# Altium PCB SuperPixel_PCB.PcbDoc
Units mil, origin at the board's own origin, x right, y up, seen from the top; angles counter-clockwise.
Board outline 3155 x 3149.61 mil, 2 copper layers (Top Layer, Bottom Layer); 61 components, 44 nets, 211 pads, 90 vias.
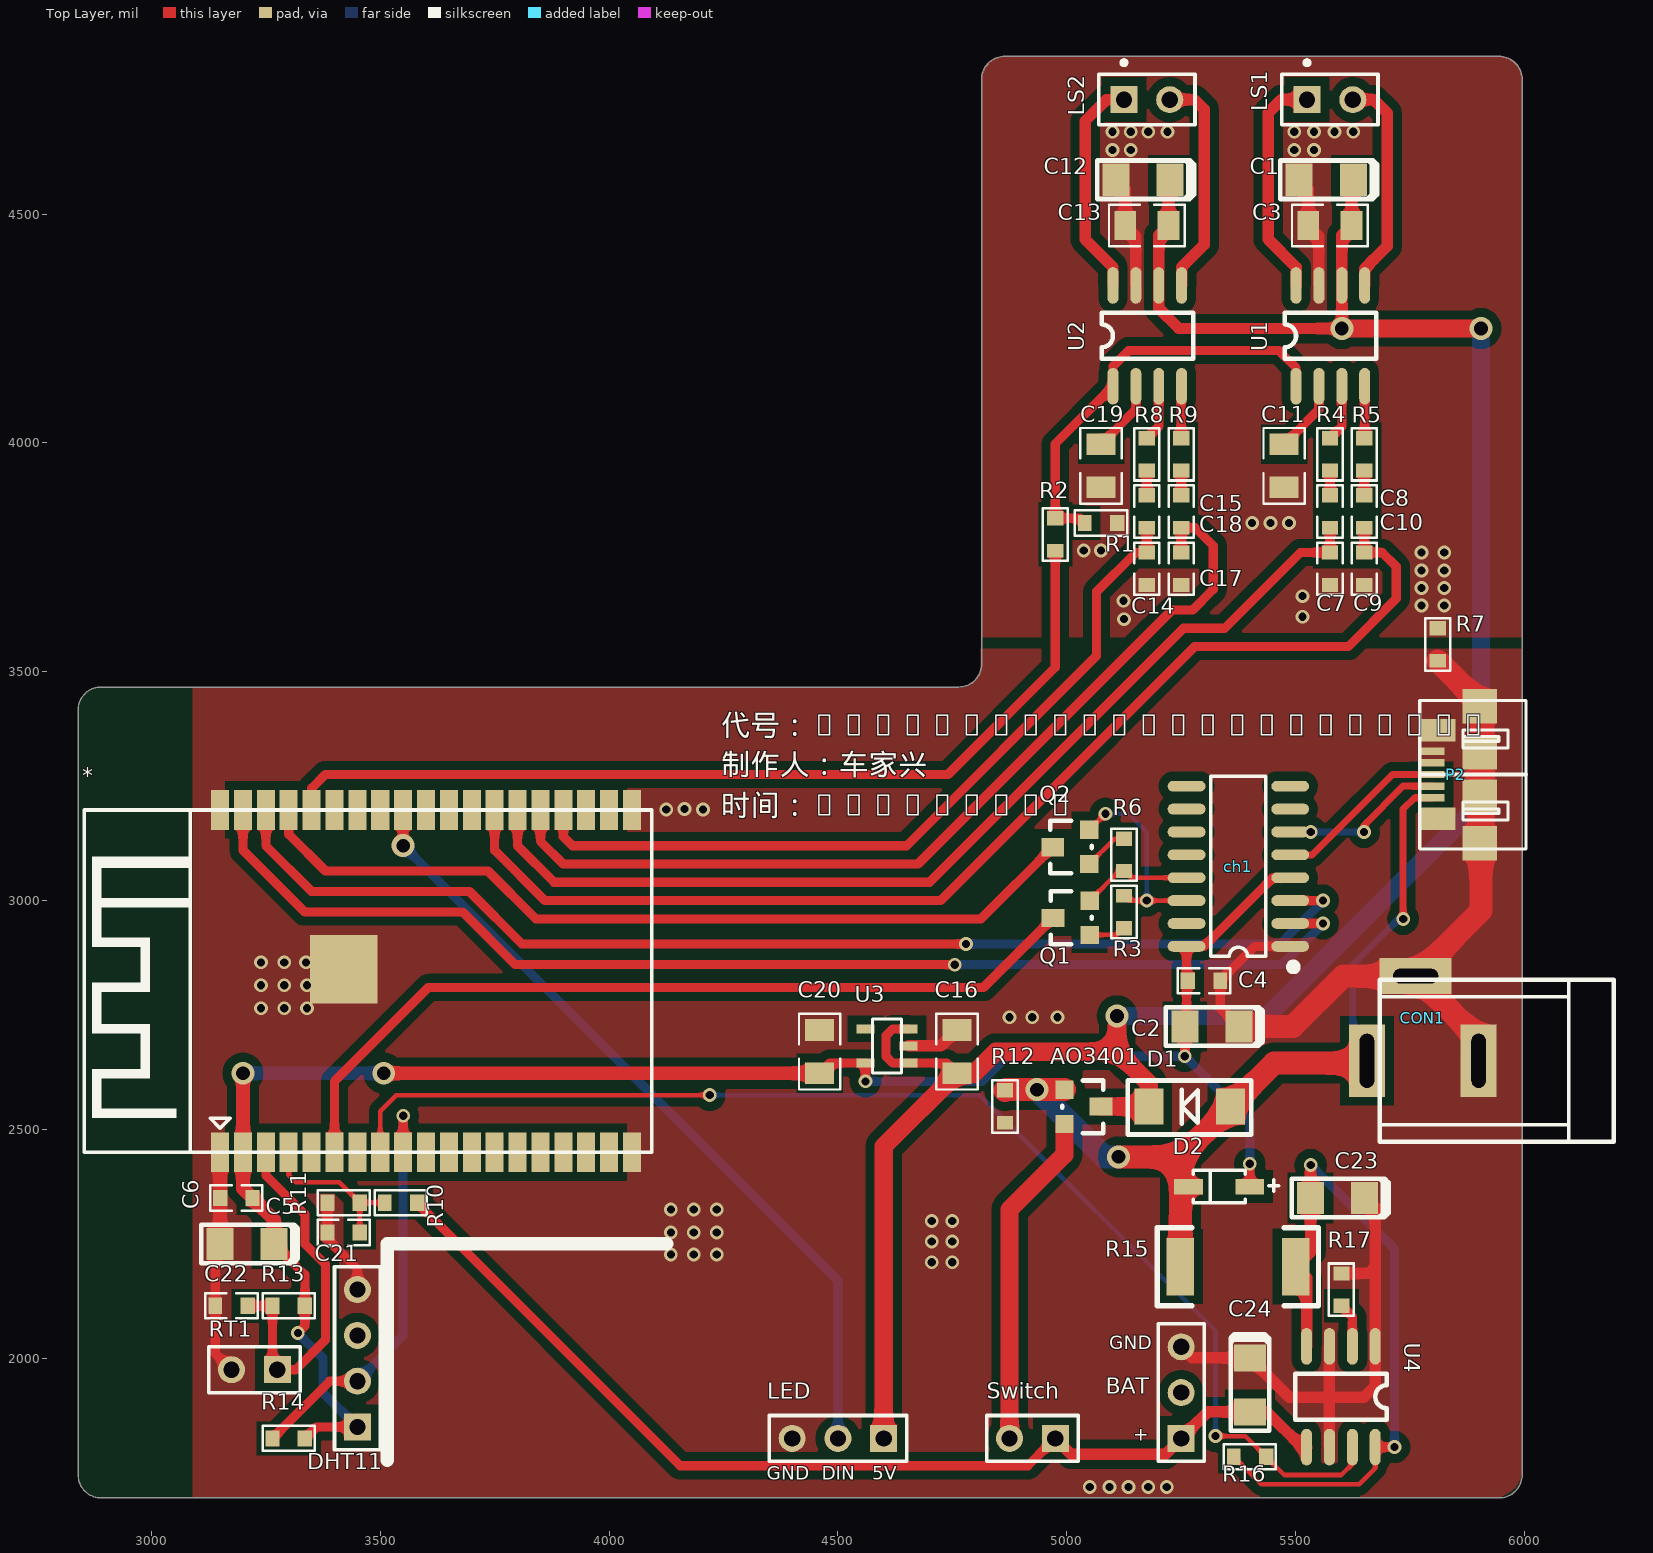
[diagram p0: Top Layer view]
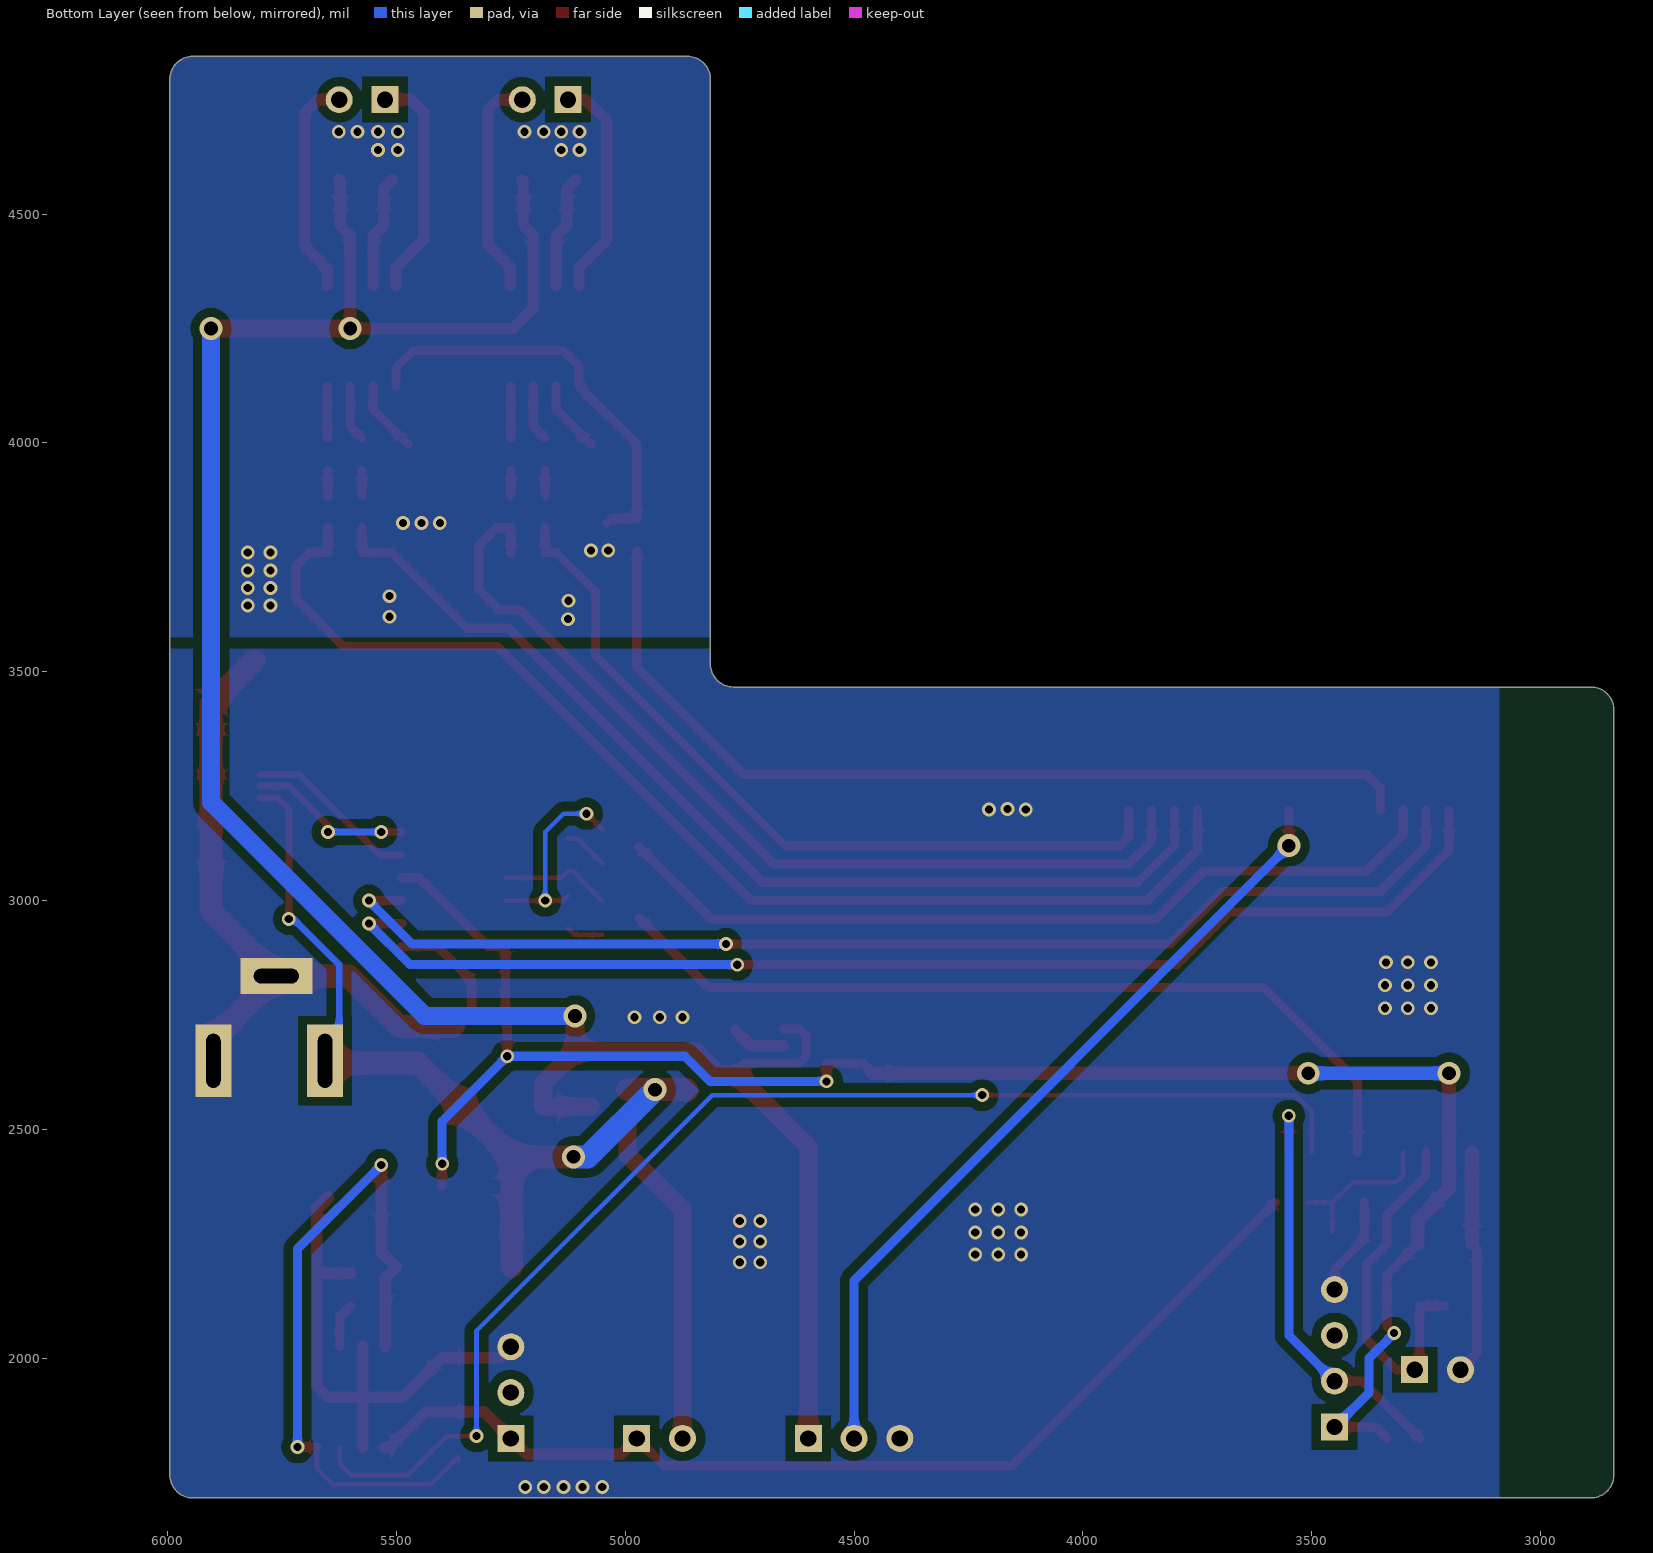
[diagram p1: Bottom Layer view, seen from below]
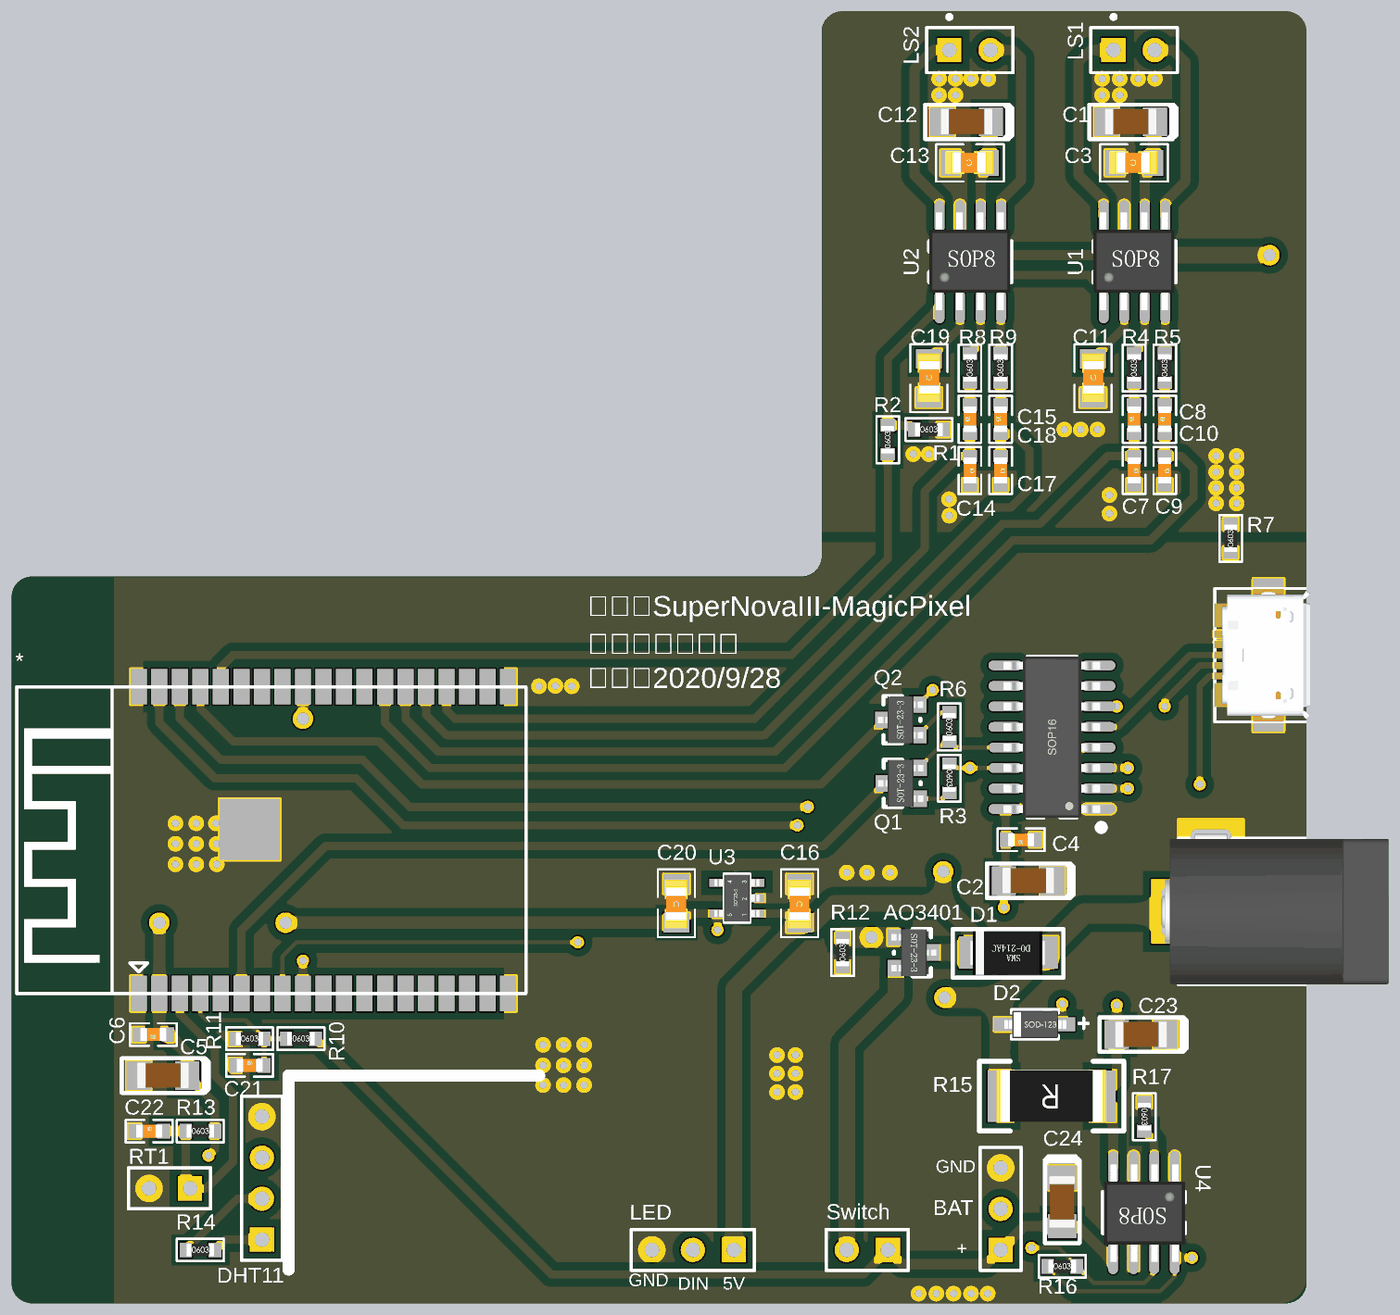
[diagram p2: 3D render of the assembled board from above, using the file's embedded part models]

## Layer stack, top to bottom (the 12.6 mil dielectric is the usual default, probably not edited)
Top Solder: solder mask 0.4, Solder Resist, Dk 3.5
Top Layer: signal copper 1.4
Dielectric 1: dielectric 12.6, FR-4, Dk 4.8
Bottom Layer: signal copper 1.4
Bottom Solder: solder mask 0.4, Solder Resist, Dk 3.5

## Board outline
2840,1745 ccw(c2890,1745) 2890,1695 5945,1695 ccw(c5945,1745) 5995,1745 5995,4794.61 ccw(c5945,4794.61) 5945,4844.61 4863.9,4844.61 ccw(c4863.9,4794.61) 4813.9,4794.61 4813.9,3516.65 cw(c4763.9,3516.65) 4763.9,3466.65 2890,3466.65 ccw(c2890,3416.65) 2840,3416.65

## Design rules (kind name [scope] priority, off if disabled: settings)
Clearance [All] p1: gap=10 ignorepadtopadclearanceinfootprint=FALSE except(0: Arc-Hole Track-Hole SMDPad-Hole THPad-Hole Via-Hole Fill-Hole Poly-Hole Region-Hole Text-Hole; 20: Arc-Poly Track-Poly SMDPad-Poly THPad-Poly Via-Poly Fill-Poly Poly-Poly)
PolygonConnect [All] p1: connectstyle=Direct reliefconductorwidth=10 reliefentries=4 polygonreliefangle="90 Angle" airgapwidth=10
RoutingVias [All] p1: holewidth=28 width=50 viastyle="Through Hole" minholewidth=28 minwidth=50 maxholewidth=28 maxwidth=50
SolderMaskExpansion [All] p1: expansion=4
Width [All] p1: maxlimit=50 minlimit=10 preferedwidth=10
30 further rules are at their usual default settings.

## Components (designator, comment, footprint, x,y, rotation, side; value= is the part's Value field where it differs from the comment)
* "ESP32-A1S Module" "ESP32-A1S Module" 3475,2825 r90 top
AO3401 "MOSFET-P" sot23 4994.37,2591.88 r270 top
BAT "Header 3" HDR1X3 5250,1825 r90 top (schematic designator P1)
C1 "Cap" 1206c 5625,4575 r180 top value=10uF
C2 "Cap" 1206c 5375,2725 r180 top value=10uF
C3 "Cap" 0805-1c 5575,4475 r180 top value=1uF
C4 "Cap" 0603c 5300,2825 r180 top value=100nF
C5 "Cap" 1206c 3267.11,2250 r180 top value=10uF
C6 "Cap" 0603c 3185.43,2350 r180 top value=0.1uF
C7 "Cap" 0603c 5575,3725 r270 top value=0.1uF
C8 "Cap" 0603c 5575,3850 r90 top value=0.1uF
C9 "Cap" 0603c 5650,3725 r270 top value=0.1uF
C10 "Cap" 0603c 5650,3850 r90 top value=0.1uF
C11 "Cap" 0805-1c 5475,3950 r90 top value=1uF
C12 "Cap" 1206c 5225,4575 r180 top value=10uF
C13 "Cap" 0805-1c 5175,4475 r180 top value=1uF
C14 "Cap" 0603c 5175,3725 r270 top value=0.1uF
C15 "Cap" 0603c 5175,3850 r90 top value=0.1uF
C16 "Cap" 0805-1c 4760,2670 r270 top value=1uF
C17 "Cap" 0603c 5250,3725 r270 top value=0.1uF
C18 "Cap" 0603c 5250,3850 r90 top value=0.1uF
C19 "Cap" 0805-1c 5075,3950 r90 top value=1uF
C20 "Cap" 0805-1c 4460,2670 r270 top value=1uF
C21 "Cap" 0603c 3420,2275 r0 top value=100nF
C22 "Cap" 0603c 3175,2114.57 r0 top value=0.1uF
C23 "Cap" 1206c 5650,2350 r180 top value=10uF
C24 "Cap" 1206c 5400,2000 r270 top value=10uF
ch1 "CH340C" SOP16_M 5375,3075 r180 top
CON1 "3.5*1.3" DC-005 5900,2650 r0 top
D1 "SS54" SMA 5350,2550 r180 top
D2 "MBR0520" SOD123 5400,2375 r0 top
DHT11 "Header 4" HDR1X4 3450,1850 r90 top
LED "Header 3" HDR1X3 4600,1825 r180 top
LS1 "Speaker" PIN2 5525,4750 r0 top
LS2 "Speaker" PIN2 5125,4750 r0 top
P2 "Header 6" USB-MICRO 5850,3275 r90 top
Q1 "s8050" sot-23 5050.63,2920.12 r90 top
Q2 "s8050" sot-23 5050,3075 r90 top
R1 "Res1" 0603r 5075,3825 r0 top value=10k
R2 "Res1" 0603r 4975,3800 r90 top value=1K
R3 "Res1" 0603r 5125,2975 r270 top value=10k
R4 "Res1" 0603r 5575,3975 r90 top value=30k
R5 "Res1" 0603r 5650,3975 r90 top value=30k
R6 "Res1" 0603r 5125,3100 r90 top value=10k
R7 "Res1" 0603r 5810.5,3559.57 r90 top value=0
R8 "Res1" 0603r 5175,3975 r90 top value=30k
R9 "Res1" 0603r 5250,3975 r90 top value=30k
R10 "Res1" 0603r 3545,2340 r0 top value=10k
R11 "Res1" 0603r 3420,2340 r0 top value=1k
R12 "Res1" 0603r 4865,2550 r90 top value=10k
R13 "Res1" 0603r 3300,2114.57 r0 top value=10k
R14 "Res1" 0603r 3300,1825 r0 top value=10k
R15 "Res1" 2512-r 5500,2200 r0 top value=0.4
R16 "Res1" 0603r 5400,1785 r0 top value=10k
R17 "Res1" 0603r 5600,2150 r270 top value=5k
RT1 "Res Thermal" HDR1X2 3275,1975 r180 top
Switch "SW-SPST" HDR1X2 4975,1825 r180 top (schematic designator S1)
U1 "NS4150" SOP8 5500,4125 r90 top
U2 "NS4150" SOP8 5100,4125 r90 top
U3 "RT9013-33GB" sot23-5 4654.49,2645 r270 top
U4 "TP4056" SOP8 5675,2025 r270 top

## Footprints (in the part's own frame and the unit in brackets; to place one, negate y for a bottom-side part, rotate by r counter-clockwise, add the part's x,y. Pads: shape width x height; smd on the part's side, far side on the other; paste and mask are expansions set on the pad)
0603c [mm]
  rect 0.762x0.9 smd: 1(-0.9,0)
  rect 0.8x0.9 smd: 2(0.9,0)
  silkscreen extent -1.45,-0.7 1.45,0.7, body extent -0.8,-0.4 0.8,0.4, height 0.3
0603r [mm]
  rect 0.762x0.9 smd: 1(-0.9,0)
  rect 0.8x0.9 smd: 2(0.9,0)
  silkscreen extent -1.45,-0.7 1.45,0.7, body extent -0.85,-0.4 0.85,0.4, height 0.56
0805-1c [mm]
  rect 1.2x1.6 smd: 1(-1.2,0) 2(1.2,0)
  silkscreen extent -2.1,-1.15 2.1,1.15, body extent -1.46,-0.72 1.54,0.68, height 0.93
1206c [mil]
  rect 59.06x70 smd: 1(-1,0) 2(117.11,0)
  silkscreen extent -53,-42 159,42, body extent -5,-32 121,31, height 37
2512-r [mil]
  rect 60x125 smd: 1(0,0) 2(-251.97,0)
  silkscreen extent -302,-85 50,85, body extent -260,-65 8,65, height 25
DC-005 [mm] "5.5*2.1mm，DC30V,2.5A"
  rect 2x4 hole 0.8 slot 3 at 90 deg: 1(-6.2,0) 2(0,0)
  rect 4x2 hole 0.8 slot 2.5 at 0 deg: 3(-3.5,4.7)
  silkscreen extent -5.48,-4.5 7.5,4.5, body extent -6.55,-4.5 7.5,4.8, height 11.2
"ESP32-A1S Module" [mm]
  rect 2.2x1 smd: 1(-9.525,8.255) 2(-9.525,6.985) 3(-9.525,5.715) 4(-9.525,4.445) 5(-9.525,3.175) 6(-9.525,1.905) 7(-9.525,0.635) 8(-9.525,-0.635) 9(-9.525,-1.905) 10(-9.525,-3.175) 11(-9.525,-4.445) 12(-9.525,-5.715) 13(-9.525,-6.985) 14(-9.525,-8.255) 15(-9.525,-9.525) 16(-9.525,-10.795) 17(-9.525,-12.065) 18(-9.525,-13.335) 19(-9.525,-14.605) 20(9.475,-14.605) 21(9.475,-13.335) 22(9.475,-12.065) 23(9.475,-10.795) 24(9.475,-9.525) 25(9.475,-8.255) 26(9.475,-6.985) 27(9.475,-5.715) 28(9.475,-4.445) 29(9.475,-3.175) 30(9.475,-1.905) 31(9.475,-0.635) 32(9.475,0.635) 33(9.475,1.905) 34(9.475,3.175) 35(9.475,4.445) 36(9.475,5.715) 37(9.475,6.985) 38(9.475,8.255)
  rect 3.785x3.759 smd: 39(0.635,1.397)
  silkscreen extent -9.53,-15.7 9.48,15.8
HDR1X2 [mm] "Connector; Header; 2 Position"
  rect 1.5x1.5 hole 0.9: 1(0,0)
  round 1.5 hole 0.9: 2(2.54,0)
  silkscreen extent -1.27,-1.27 3.81,1.27
HDR1X3 [mm] "Connector; Header; 3 Position"
  rect 1.5x1.5 hole 0.9: 1(0,0)
  round 1.5 hole 0.9: 2(2.54,0) 3(5.08,0)
  silkscreen extent -1.27,-1.27 6.35,1.27
HDR1X4 [mm] "Connector; Header; 4 Position"
  rect 1.5x1.5 hole 0.9: 1(0,0)
  round 1.5 hole 0.9: 2(2.54,0) 3(5.08,0) 4(7.62,0)
  silkscreen extent -1.27,-1.27 8.89,1.27
PIN2 [mm] "Photosensitive Diode; 2 Leads"
  rect 1.5x1.5 hole 0.9: 1(0,0)
  round 1.5 hole 0.9: 2(2.54,0)
  silkscreen extent -1.4,-1.4 3.94,2.17
SMA [mil] "DO-214AC(2010)"
  rect 63x78.74 smd: 1(-8,0) 2(170.56,0)
  silkscreen extent -53,-57 217,61, body extent -8,-52 174,54, height 94
SOD123 [mm] "1206"
  rect 1.6x0.85 smd: 1(0,0) 2(-3.4,0)
  silkscreen extent -3.15,-0.9 1.6,0.9, body extent -3.6,-0.85 0.25,0.85, height 1.42
SOP8 [mil]
  oval 80x24 smd: 1(-1,-1) 2(-1,-51) 3(-1,-101) 4(-1,-151) 5(219,-151) 6(219,-101) 7(219,-51) 8(219,-1)
  silkscreen extent 59,-176 159,24, body extent -9,-174 229,24, height 63
SOP16_M [mm] "10.3*6.2*1.8mm（长宽高）"
  oval 2.1x0.6 smd: 1(-2.875,4.445) 2(-2.875,3.175) 3(-2.875,1.905) 4(-2.875,0.635) 5(-2.875,-0.635) 6(-2.875,-1.905) 7(-2.875,-3.175) 8(-2.875,-4.445) 9(2.875,-4.445) 10(2.875,-3.175) 11(2.875,-1.905) 12(2.875,-0.635) 13(2.875,0.635) 14(2.875,1.905) 15(2.875,3.175) 16(2.875,4.445)
  silkscreen extent -3.2,-5 1.52,5.74, body extent -3,-5 3,5, height 1.9
sot23 [mil]
  rect 40x40 smd: 1(4.88,0.63) 3(79.88,0.63)
  rect 40x50 smd: 2(41.88,80.63)
  silkscreen extent -15,-4 100,86, body extent -15,-11 99,99, height 47
sot23-5 [mm]
  rect 0.5x1 smd: 1(0,0) 2(-0.95,0) 3(-1.9,0) 4(-1.9,-2.4) 5(0,-2.4)
  silkscreen extent -2.45,-2 0.55,-0.4, body extent -2.4,-2.6 0.5,0.2, height 1.09
sot-23 [mil]
  rect 40x40 smd: 1(4.88,0.63) 2(79.88,0.63)
  rect 40x50 smd: 3(41.88,80.63)
  silkscreen extent -15,-4 100,86, body extent -15,-11 99,99, height 47
USB-MICRO [mm]
  rect 1.9x1.9 smd: 0(-3.797,-1.334) 0(-1.206,-1.333) 0(1.232,-1.333) 0(3.797,-1.333)
  rect 1.25x2 smd: 0(-2.451,1.003) 0(2.476,1.003)
  rect 0.4x1.4 smd: 1(-1.283,1.333) 2(-0.635,1.333) 3(0.013,1.333) 4(0.66,1.333) 5(1.308,1.333)
  silkscreen extent -4.13,-3.91 4.13,1.99, body extent -4.1,-3.91 4.1,2.02, height 2.77

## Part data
AO3401: "P-Channel MOSFET"
BAT LED: "Header, 3-Pin"
C1 C2 C3 C4 C5 C6 C7 C8 C9 C10 C11 C12 C13 C14 C15 C16 C17 C18 C19 C20 C21 C22 C23 C24: "Capacitor"
ch1: library part CH340G, "串口转USB"
CON1: library part P-DC, "低压电源接口"
D1 D2: library part "D Schottky", "Schottky Diode"
DHT11: "Header, 4-Pin"
LS1 LS2: "Loudspeaker"
P2: "Header, 6-Pin"
Q1 Q2: library part NPN, "NPN Bipolar Transistor"
R1 R2 R3 R4 R5 R6 R7 R8 R9 R10 R11 R12 R13 R14 R15 R16 R17: "Resistor"
RT1: "Thermistor"
Switch: "Single-Pole, Single-Throw Switch"

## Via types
v1: diameter 30, hole 18, Top Layer to Bottom Layer, 82 vias
v2: diameter 50, hole 30, Top Layer to Bottom Layer, 8 vias

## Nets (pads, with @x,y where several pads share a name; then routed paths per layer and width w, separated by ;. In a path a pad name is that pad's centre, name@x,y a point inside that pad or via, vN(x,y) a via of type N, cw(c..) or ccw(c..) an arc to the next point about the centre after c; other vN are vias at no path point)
3V3: *.2 C2.2 C4.2 C5.1 C6.1 C20.2 ch1.4 ch1.16 D2.1 DHT11.1 R13.2 R14.2 U3.5 | length 4019
  Top Layer w20: C5.1 3335.43,2182.68 R13.2 3335.43,2070.43 v1(3320,2055) ; R14.2 3360.43,1850 DHT11.1 ; C20.2 4482.24,2645 U3.5 v1(4560,2605) ; v1(5257.89,2660) C2.2 5261.81,2728.92 ch1.16 5300,2900 5450,3050 ch1.4 ; D2.1 v1(5400,2425)
  Top Layer w30: v2(3200,2622.76) *.2 3200,2370.87 C6.1 3268.11,2302.76 C5.1 ; v2(3507.76,2622.76) C20.2 C20.2@4459.2,2623.55
  Bottom Layer w20: v1(3320,2055) 3375,2000 3375,1925 DHT11.1 ; v1(4560,2605) 4815,2605 4870,2660 v1(5257.89,2660) 5400,2517.89 v1(5400,2425)
  Bottom Layer w30: v2(3200,2622.76) v2(3507.76,2622.76)
+5: AO3401.1 CON1.1 D1.1 D2.2 P2.1 R12.2 R15.2 | length 1924.2
  Top Layer w15: v1(5735,2960) 5735,3200 5759.5,3224.5 P2.1
  Top Layer w50: R12.2 4866.57,2587 v2(4935,2587) AO3401.1 ; v2(5112.92,2440.03) 5248.03,2440.03 ; R15.2 5248.03,2440.03 ; CON1.1@5655.91,2645 5453,2645 D1.1 5248.03,2440.03
  Bottom Layer w15: CON1.1 5625,2680.91 5625,2860 5725,2960 v1(5735,2960)
  Bottom Layer w50: v2(4935,2587) 5081.97,2440.03 v2(5112.92,2440.03)
ADC_BAT: *.4 C21.2 R10.1 R11.2 | length 349.4
  Top Layer w10: *.4 3300,2400 3315,2385 3410.43,2385 R11.2 ; C21.2 R11.2 ; R10.1 R11.2
ADC_LIGHT: *.3 C22.2 R13.1 RT1.1 | length 793.8
  Top Layer w20: C22.2 R13.1 3264.57,1985.43 RT1.1 3315,1975 3380,2040 3380,2205.43 3335.43,2250 3335.43,2314.57 3250,2400 *.3
CHARGGING: *.8 R16.2 U4.7 | length 2754
  Top Layer w10: *.8 3500,2540 3535,2575 v1(4220,2575) ; v1(5325,1830) 5390.43,1830 R16.2 5475.43,1745 5600,1745 5624,1769 U4.7
  Bottom Layer w10: v1(4220,2575) 4810,2575 5325,2060 v1(5325,1830)
CTRL: R1.1 R2.2 U1.1 U2.1 | length 923
  Top Layer w20: R1.1 5029.13,3835.43 R2.2 4975,3998 U2.1 5101,4167.72 5134.89,4201.61 5463.39,4201.61 5501,4164 U1.1
D+: ch1.5 P2.3 | length 382
  Top Layer w15: ch1.5 5536,3100 5711.5,3275.5 P2.3
D-: ch1.6 P2.2 | length 358.7
  Top Layer w15: ch1.6 v1(5532.89,3150) ; v1@5649.5,3150.5 5649.5,3164.5 5735,3250 P2.2
  Bottom Layer w15: v1(5532.89,3150) v1(5649.5,3150)
DHT_DATA: *.9 DHT11.2 R14.1 | length 938.6
  Top Layer w20: R14.1 3389.57,1950 DHT11.2 ; *.9 v1(3550,2530)
  Bottom Layer w20: DHT11.2 3550,2050 v1(3550,2530)
GND: *.1 *.19 *.20 *.38 *.39 BAT.3 C2.1 C4.1 C5.2 C6.2 C16.1 C20.1 C21.1 C22.1 C23.1 C24.1 ch1.1 CON1.2 CON1.3 DHT11.4 LED.3 P2.0 P2.4 P2.5 R7.1 R11.1 R12.1 R17.1 RT1.2 U3.2 U4.1 U4.3 U4.6 | length 4020.7
  Top Layer w20: C5.2 3139.57,2239.57 C22.1 3139.57,2010.43 RT1.2 ; R11.1 C21.1 3384.57,2260.87 3450,2195.43 DHT11.4@3450,2175 ; C2.1 5335.43,2765.57 C4.1 5410.43,2900 ch1.1
  Top Layer w25: U3.2 4725.16,2682.4 C16.1 ; BAT.3 5274,2001 C24.1 5486,1915 5570,1915 ; U4.6 5574,1911 5570,1915 ; U4.3 5574,1919 5570,1915 ; R17.1 5659.43,2185.43 5674,2200 ; C23.1@5674,2327 5674,2200 ; 5570,1915 5649.43,1915 5674,1939.57 U4.1 5674,2200
  Top Layer w30: C5.2 C6.2 *.1 ; C23.1 C23.1@5674,2327
  Top Layer w50: C2.1 5494,2725 5604.04,2835.04 CON1.3 ; R7.1 5905,3429.63 5905,3323.5 5905,2977.83 ; CON1.2 5900,2697.24 CON1.3 ; P2.0@5905,3227.5 5905,2977.83 ; CON1.3 5905,2977.83
  other v1: 5050,1718.56 5093.29,1718.56 5135,1718.56 5177.82,1718.56 5218.41,1718.56 4705,2209.71 4750,2210 4135,2226.83 4185,2226.83 4235,2226.83 4705,2255 4750,2255 4135,2275 4185,2275 4235,2275 4705,2300 4750,2300 4135,2325 4185,2325 4235,2325 4875,2745 4924.37,2745 4980,2745 3239.31,2765 3290,2765 3340,2765 3239.31,2815 3290,2815 3339.82,2815 3239.31,2865 3290,2865 3337.9,2865 4125,3199.14 4205,3199.14 4165,3200
GPIO0: *.6 Q1.3 | length 1872.9
  Top Layer w20: *.6 3400,2605 3605,2810 4818,2810 Q1.3
GPIO18: *.30 LED.2 | length 1766.5
  Top Layer w20: v2(3550,3120) *.30
  Bottom Layer w20: v2(3550,3120) 4500,2170 LED.2
GPIO21: *.34 R2.1 | length 2036.6
  Top Layer w20: *.34 3350,3245.5 3380,3275.5 4740.5,3275.5 4975,3510 R2.1
NetAO3401_3: AO3401.3 Switch.2 | length 736.7
  Top Layer w40: Switch.2 4875,2325 4995,2445 AO3401.3
NetC8_2: C8.2 R4.1 | length 54.1
  Top Layer w20: C8.2 R4.1
NetC10_2: C10.2 R5.1 | length 54.1
  Top Layer w20: C10.2 R5.1
NetC11_2: C11.2 U1.2 | length 158.2
  Top Layer w20: C11.2 5551,4073.24 U1.2
NetC15_2: C15.2 R8.1 | length 54.1
  Top Layer w20: C15.2 R8.1
NetC18_2: C18.2 R9.1 | length 54.1
  Top Layer w20: C18.2 R9.1
NetC19_2: C19.2 U2.2 | length 158.2
  Top Layer w20: C19.2 5151,4073.24 U2.2
NetC23_2: C23.2 R15.1 R16.1 U4.4 U4.8 | length 1558
  Top Layer w10: R16.1@5364.57,1775.43 R16.1 5424.57,1725 5639,1725 5674,1760 U4.8
  Top Layer w20: U4.8 v1(5716,1806)
  Top Layer w25: U4.4 5524,2176 R15.1 5532.89,2232.89 C23.2 v1(5532.89,2422.11)
  Bottom Layer w20: v1(5532.89,2422.11) 5716,2239 v1(5716,1806)
Netch1_13: ch1.13 Q1.2 R6.1 | length 244.6
  Top Layer w10: Q1.2 5114.57,3064.57 R6.1 5139.57,3050 ch1.13
Netch1_14: ch1.14 Q2.2 R3.1 | length 447.9
  Top Layer w10: Q2.2 v1(5084.49,3190) ; R3.1 5135.43,3000 v1(5175,3000) ch1.14
  Bottom Layer w10: v1(5084.49,3190) 5135,3190 5175,3150 v1(5175,3000)
NetLS1_1: LS1.1 U1.8 | length 499.4
  Top Layer w25: U1.8 5501,4384 5440,4445 5440,4721.25 5468.75,4750 LS1.1
NetLS1_2: LS1.2 U1.5 | length 484.1
  Top Layer w25: LS1.2 5670.64,4750 5700,4720.64 5700,4430 5651,4381 U1.5
NetLS2_1: LS2.1 U2.8 | length 488.9
  Top Layer w25: U2.8 5101,4384 5040,4445 5040,4703.36 5086.64,4750 LS2.1
NetLS2_2: LS2.2 U2.5 | length 489
  Top Layer w25: LS2.2 5278.95,4750 5300,4728.95 5300,4433.19 5251,4384.19 U2.5
NetQ1_1: Q1.1 R3.2 | length 81
  Top Layer w10: Q1.1 5110.43,2925 R3.2
NetQ2_1: Q2.1 R6.2 | length 98.6
  Top Layer w10: Q2.1 5104.92,3135.43 R6.2
NetR4_2: R4.2 U1.3 | length 124.3
  Top Layer w20: R4.2 5601,4036.43 U1.3
NetR5_2: R5.2 U1.4 | length 114
  Top Layer w20: R5.2 5651,4011.43 U1.4
NetR8_2: R8.2 U2.3 | length 124.3
  Top Layer w20: R8.2 5201,4036.43 U2.3
NetR9_2: R9.2 U2.4 | length 114
  Top Layer w20: R9.2 5250,4123 U2.4
NetR17_2: R17.2 U4.2 | length 99.9
  Top Layer w20: R17.2 5624,2090.57 U4.2 U4.2@5625,2027
PGND: C1.2 C3.2 C7.2 C9.2 C11.1 C12.2 C13.2 C14.2 C17.2 C19.1 R1.2 R7.2 U1.7 U2.7 | length 497.7
  Top Layer w25: C12.2 5127.76,4555.13 C13.2 5151,4451.76 U2.7 ; C1.2 5527.76,4555.13 C3.2 5551,4451.76 U1.7
  other v1: 5125,3615 5515,3620 5775,3644.87 5825,3644.87 5124.18,3655 5515,3665.26 5775,3682.83 5825,3682.83 5775,3721.27 5825,3721.27 5775,3760.43 5825,3760.43 5036.97,3765 5074.57,3765 5405,3825 5445,3825 5485.51,3825 5100,4640 5140,4640 5497.11,4640 5540,4640 5100,4680 5140,4680 5177.82,4680 5220,4680 5497.11,4680 5540,4680 5585,4680 5626,4680
RST: *.35 Q2.3 | length 1864
  Top Layer w20: *.35 3300,3145 3380.43,3064.57 3735.43,3064.57 3840,2960 4812.49,2960 Q2.3
RXD: *.36 ch1.3 | length 2588.2
  Top Layer w20: *.36 3250,3120 3350,3020 3695,3020 3810,2905 v1(4780,2905) ; ch1.3 v1(5560,3000)
  Bottom Layer w20: v1(4780,2905) 5465,2905 v1(5560,3000)
SPOLN: *.26 C9.1 C10.1 | length 2583.7
  Top Layer w20: *.26 3750,3110 3860,3000 4724,3000 5279,3555 5615,3555 5720,3660 5720,3730 5689.57,3760.43 C9.1 C10.1
SPOLP: *.25 C7.1 C8.1 | length 2238.7
  Top Layer w20: *.25 3800,3120 3880,3040 4700,3040 5255,3595 5345,3595 5510.43,3760.43 C7.1 C8.1
SPORN: *.24 C17.1 C18.1 | length 2042.8
  Top Layer w20: *.24 3850,3130 3900,3080 4675,3080 5230,3635 5275,3635 5320,3680 5320,3775 5280.43,3814.57 C18.1 C17.1
SPORP: *.23 C14.1 C15.1 | length 1742.7
  Top Layer w20: *.23 3900,3140 3920,3120 4650,3120 5065,3535 5065,3675 5150.43,3760.43 C14.1 C15.1
TXD: *.37 ch1.2 | length 2660.7
  Top Layer w20: *.37 3200,3110 3335,2975 3680,2975 3795,2860 v1(4755,2860) ; ch1.2 v1(5560,2950)
  Bottom Layer w20: v1(4755,2860) 5470,2860 v1(5560,2950)
Vbat: BAT.1 C24.2 R10.2 Switch.1 U4.5 | length 2291.4
  Top Layer w20: R10.2 4155.43,1765 4915,1765 Switch.1
  Top Layer w25: Switch.1 5010,1790 5215,1790 BAT.1 5307.89,1882.89 C24.2 5437.11,1882.89 5514,1806 U4.5
VBUS: AO3401.2 C1.1 C3.1 C12.1 C13.1 C16.2 D1.2 LED.1 U1.6 U2.6 U3.1 U3.3 | length 5209.3
  Top Layer w20: U3.3 4619.8,2719.8 4605,2705 4605,2660 4620,2645 U3.1 4737.76,2645 C16.2
  Top Layer w25: C12.1 5222.24,4571.24 C13.1 5201,4453.76 U2.6 5201,4294 5245,4250 v2(5601,4250) U1.6 5601,4453.76 C3.1 5622.24,4571.24 C1.1
  Top Layer w40: LED.1 4600,2462.76 C16.2 ; C16.2@4760,2620 4795,2620 4845,2670 5110,2670 ; AO3401.2 D1.2 5179.44,2600.56 5110,2670 ; v2(5110,2747.89) 5110,2670 ; v2(5601,4250) v2(5905,4250)
  Bottom Layer w40: v2(5110,2747.89) 5437.89,2747.89 5905,3215 v2(5905,4250)
pads on no net: *.5 *.7 *.10 *.11 *.12 *.13 *.14 *.15 *.16 *.17 *.18 *.21 *.22 *.27 *.28 *.29 *.31 *.32 *.33 BAT.2 ch1.7 ch1.8 ch1.9 ch1.10 ch1.11 ch1.12 ch1.15 DHT11.3 U3.4

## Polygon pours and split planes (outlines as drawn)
GND on Top Layer "TopGND" (solid, pour order 0): 3090,3465 3090,1695 5930,1695 ccw(c5930,1760) 5995,1760 5995,3550 4812.49,3550 4812.49,3512.49 cw(c4765,3512.49) 4765,3465
PGND on Top Layer "TopGND" (solid, pour order 4): 5995,3575 4815,3575 4815,4795 cw(c4865,4795) 4865,4845 5945,4845 cw(c5945,4795) 5995,4795
GND on Bottom Layer "TopGND" (solid, pour order 2): 3090,3465 3090,1695 5940,1695 ccw(c5940,1750) 5995,1750 5995,3550 4815,3550 4815,3520 cw(c4760,3520) 4760,3465
PGND on Bottom Layer "TopGND" (solid, pour order 6): 5995,3575 4815,3575 4815,4795 cw(c4865,4795) 4865,4845 5945,4845 cw(c5945,4795) 5995,4795

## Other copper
Top Layer:
  pour cut-out: 5317.64,2411.73 5317.64,2338.27 5348.5,2338.27 5348.5,2411.73
  pour cut-out: 3350,3135.43 3395.43,3090 3730,3090 3730,3140 3725,3145
  pour cut-out: 5009.37,3076.88 4951.28,3076.88 4801.71,2927.31 4801.71,2891.93 4778.78,2869.01 4778.78,2844.32 4793.1,2830 4838,2830 5010,3002
  pour cut-out: 4930.75,3156.88 4930.75,3112.17 4803.57,2985 4745,2985 4745,2999.65 4915.35,3170

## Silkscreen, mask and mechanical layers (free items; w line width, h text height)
Top Overlay:
  lines w30: 3515,1777.56 3515,2250 4125.24,2250
  text "代号：SuperNovaIII-MagicPixel" at 4245,3345 h80
  text "制作人：车家兴" at 4245,3260 h80
  text "时间：2020/9/28" at 4245,3170 h80
  text "GND" at 5093.29,2010 h50
  text "+" at 5145,1810 h50
  text "GND" at 4345,1725 h50
  text "DIN" at 4465,1725 h50
  text "5V" at 4575,1725 h50
Mechanical 1:
  the board outline again, w30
